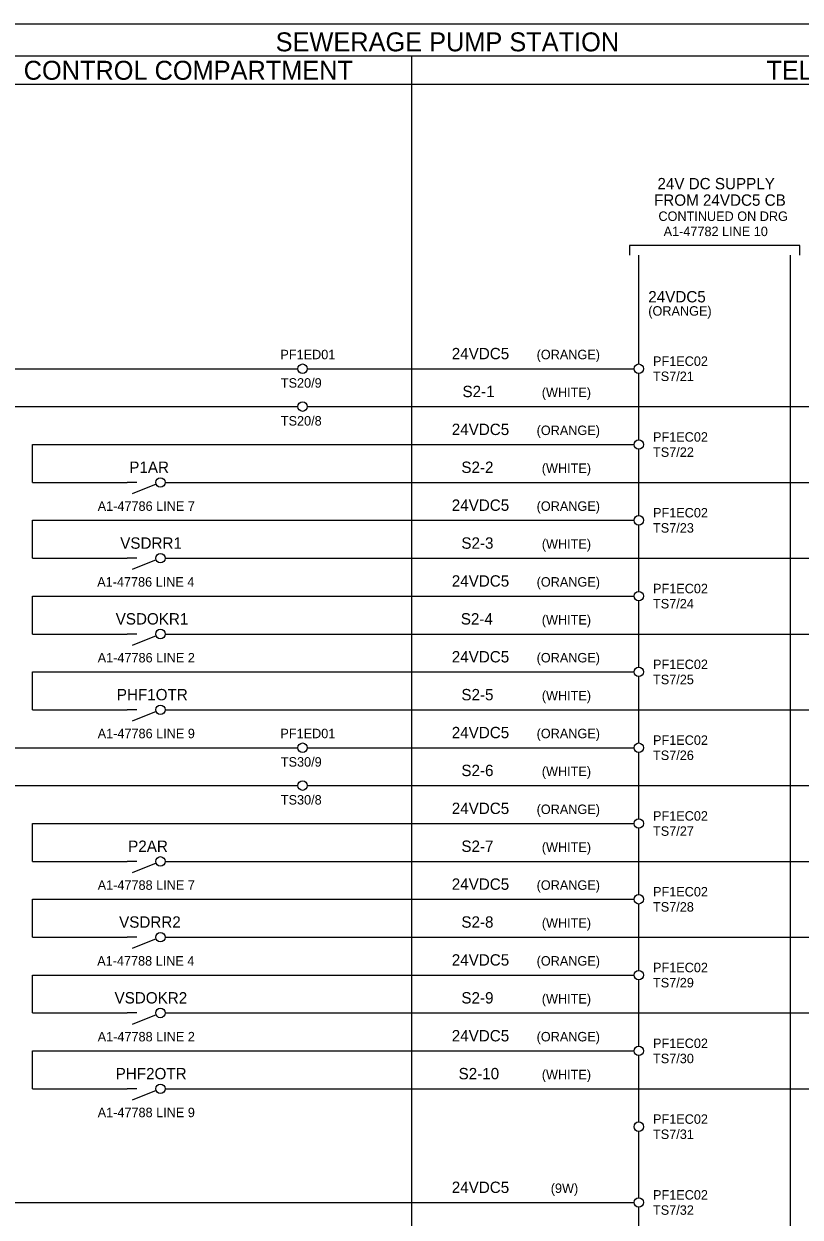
# Model space of a CAD drawing. Extents: x 0 to 841, y 0 to 594.
# Drawn here: x 447.7 to 652.6, y 266.1 to 581 of the extents above; entities that cross this region are included whole.
import ezdxf

# ---------------------------------------------------------------- set-up
doc = ezdxf.new("R2010")
doc.units = 0
for name, color, linetype in [('A1BORDER', 7, 'Continuous'), ('Default', 7, 'Continuous'), ('Level 1', 7, 'Continuous'), ('Level 10', 7, 'Continuous'), ('Level 2', 7, 'Continuous'), ('Level 5', 7, 'Continuous')]:
    doc.layers.add(name, color=color, linetype=linetype)

msp = doc.modelspace()

# ---------------------------------------------------------------- linework, layer by layer
at = {"layer": 'A1BORDER'}
msp.add_line((28, 581), (829, 581), dxfattribs=at)
at = {"layer": 'Default'}
msp.add_line((650, 140), (650, 520), dxfattribs=at)
at = {"layer": 'Level 1'}
for p, q in [((829, 572.5), (160, 572.5)), ((550, 572.5), (550, 57)), ((829, 565), (160, 565)), ((610, 491.25), (610, 520)), ((320, 490), (520, 490)), ((520, 490), (520, 490)), ((522.5, 490), (522.5, 490)), ((522.5, 490), (608.75, 490)), ((610, 471.25), (610, 488.75)), ((360, 480), (520, 480)), ((520, 480), (520, 480)), ((522.5, 480), (522.5, 480)), ((522.5, 480), (690, 480)), ((450, 460), (450, 470)), ((450, 470), (608.75, 470)), ((610, 451.25), (610, 468.75)), ((450, 460), (475, 460)), ((477.5, 460), (475, 460)), ((475, 460), (475, 460)), ((485, 460), (690, 460)), ((485, 460), (485, 460)), ((450, 440), (450, 450)), ((450, 450), (608.75, 450)), ((610, 431.25), (610, 448.75)), ((450, 440), (475, 440)), ((477.5, 440), (475, 440)), ((475, 440), (475, 440)), ((485, 440), (690, 440)), ((485, 440), (485, 440)), ((450, 430), (608.75, 430)), ((450, 420), (450, 430)), ((610, 411.25), (610, 428.75)), ((450, 420), (475, 420)), ((477.5, 420), (475, 420)), ((475, 420), (475, 420)), ((485, 420), (690, 420)), ((485, 420), (485, 420)), ((450, 410), (608.75, 410)), ((450, 400), (450, 410)), ((610, 391.25), (610, 408.75)), ((450, 400), (475, 400)), ((477.5, 400), (475, 400)), ((475, 400), (475, 400)), ((485, 400), (690, 400)), ((485, 400), (485, 400)), ((320, 390), (520, 390)), ((520, 390), (520, 390)), ((522.5, 390), (522.5, 390)), ((522.5, 390), (608.75, 390)), ((610, 371.25), (610, 388.75)), ((360, 380), (520, 380)), ((520, 380), (520, 380)), ((522.5, 380), (522.5, 380)), ((522.5, 380), (690, 380)), ((450, 360), (450, 370)), ((450, 370), (608.75, 370)), ((610, 351.25), (610, 368.75)), ((450, 360), (475, 360)), ((477.5, 360), (475, 360)), ((475, 360), (475, 360)), ((485, 360), (690, 360)), ((485, 360), (485, 360)), ((450, 340), (450, 350)), ((450, 350), (608.75, 350)), ((610, 331.25), (610, 348.75)), ((450, 340), (475, 340)), ((477.5, 340), (475, 340)), ((475, 340), (475, 340)), ((485, 340), (690, 340)), ((485, 340), (485, 340)), ((450, 330), (608.75, 330)), ((450, 320), (450, 330)), ((610, 311.25), (610, 328.75)), ((450, 320), (475, 320)), ((477.5, 320), (475, 320)), ((475, 320), (475, 320)), ((485, 320), (690, 320)), ((485, 320), (485, 320)), ((450, 310), (608.75, 310)), ((450, 300), (450, 310)), ((610, 291.25), (610, 308.75)), ((450, 300), (475, 300)), ((477.5, 300), (475, 300)), ((475, 300), (475, 300)), ((485, 300), (690, 300)), ((485, 300), (485, 300)), ((610, 271.25), (610, 288.75)), ((272.5, 270), (608.75, 270)), ((610, 251.25), (610, 268.75))]:
    msp.add_line(p, q, dxfattribs=at)
msp.add_lwpolyline([(652.5, 520), (652.5, 522.5), (607.5, 522.5), (607.5, 520)], dxfattribs=at)
at = {"layer": 'Level 10'}
for p, q in [((482.59, 459.54), (476.25, 457)), ((482.59, 439.54), (476.25, 437)), ((482.59, 419.54), (476.25, 417)), ((482.59, 399.54), (476.25, 397)), ((482.59, 359.54), (476.25, 357)), ((482.59, 339.54), (476.25, 337)), ((482.59, 319.54), (476.25, 317)), ((482.59, 299.54), (476.25, 297))]:
    msp.add_line(p, q, dxfattribs=at)
for centre in [(521.25, 490), (610, 490), (521.25, 480), (610, 470), (483.75, 460), (610, 450), (483.75, 440), (610, 430), (483.75, 420), (610, 410), (483.75, 400), (521.25, 390), (610, 390), (521.25, 380), (610, 370), (483.75, 360), (610, 350), (483.75, 340), (610, 330), (483.75, 320), (610, 310), (483.75, 300), (610, 290), (610, 270)]:
    msp.add_circle(centre, 1.25, dxfattribs=at)

# ---------------------------------------------------------------- texts
at = {"layer": 'Level 1'}
for s, height, p in [('SEWERAGE PUMP STATION', 5, (514.16, 573.75)), ('CONTROL COMPARTMENT', 5, (447.65, 566.25)), ('TELEMETRY COMPARTMENT', 5, (643.66, 566.25)), ('24V DC SUPPLY', 3, (614.91, 537.34)), ('FROM 24VDC5 CB', 3, (614.01, 533)), ('CONTINUED ON DRG', 2.5, (615.18, 529)), ('A1-47782 LINE 10', 2.5, (616.55, 525)), ('24VDC5', 3, (612.5, 507.5)), ('(ORANGE)', 2.5, (612.5, 504)), ('PF1ED01', 2.5, (515.4, 492.5)), ('24VDC5', 3, (560.63, 492.5)), ('(ORANGE)', 2.5, (583.03, 492.5)), ('PF1EC02', 2.5, (613.75, 490.75)), ('TS7/21', 2.5, (613.75, 486.75)), ('TS20/9', 2.5, (515.52, 485)), ('S2-1', 3, (563.46, 482.5)), ('(WHITE)', 2.5, (584.39, 482.5)), ('TS20/8', 2.5, (515.52, 475)), ('24VDC5', 3, (560.63, 472.5)), ('(ORANGE)', 2.5, (583.03, 472.5)), ('PF1EC02', 2.5, (613.75, 470.75)), ('TS7/22', 2.5, (613.75, 466.75)), ('S2-2', 3, (563.16, 462.5)), ('(WHITE)', 2.5, (584.39, 462.5)), ('24VDC5', 3, (560.63, 452.5)), ('(ORANGE)', 2.5, (583.03, 452.5)), ('PF1EC02', 2.5, (613.75, 450.75)), ('TS7/23', 2.5, (613.75, 446.75)), ('S2-3', 3, (563.17, 442.5)), ('(WHITE)', 2.5, (584.4, 442.5)), ('24VDC5', 3, (560.63, 432.5)), ('(ORANGE)', 2.5, (583.03, 432.5)), ('PF1EC02', 2.5, (613.75, 430.75)), ('TS7/24', 2.5, (613.75, 426.75)), ('S2-4', 3, (563.02, 422.5)), ('(WHITE)', 2.5, (584.4, 422.5)), ('24VDC5', 3, (560.63, 412.5)), ('(ORANGE)', 2.5, (583.03, 412.5)), ('PF1EC02', 2.5, (613.75, 410.75)), ('TS7/25', 2.5, (613.75, 406.75)), ('S2-5', 3, (563.17, 402.5)), ('(WHITE)', 2.5, (584.4, 402.5)), ('PF1ED01', 2.5, (515.4, 392.5)), ('24VDC5', 3, (560.63, 392.5)), ('(ORANGE)', 2.5, (583.03, 392.5)), ('PF1EC02', 2.5, (613.75, 390.75)), ('TS30/9', 2.5, (515.52, 385)), ('TS7/26', 2.5, (613.75, 386.75)), ('S2-6', 3, (563.17, 382.5)), ('(WHITE)', 2.5, (584.4, 382.5)), ('TS30/8', 2.5, (515.52, 375)), ('24VDC5', 3, (560.63, 372.5)), ('(ORANGE)', 2.5, (583.03, 372.5)), ('S2-7', 3, (563.17, 362.5)), ('(WHITE)', 2.5, (584.4, 362.5)), ('24VDC5', 3, (560.63, 352.5)), ('(ORANGE)', 2.5, (583.03, 352.5)), ('S2-8', 3, (563.17, 342.5)), ('(WHITE)', 2.5, (584.4, 342.5)), ('24VDC5', 3, (560.63, 332.5)), ('(ORANGE)', 2.5, (583.03, 332.5)), ('S2-9', 3, (563.17, 322.5)), ('(WHITE)', 2.5, (584.4, 322.5)), ('24VDC5', 3, (560.63, 312.5)), ('(ORANGE)', 2.5, (583.03, 312.5)), ('S2-10', 3, (562.43, 302.5)), ('(WHITE)', 2.5, (584.4, 302.5)), ('24VDC5', 3, (560.63, 272.5)), ('(9W)', 2.5, (586.76, 272.5))]:
    msp.add_text(s, height=height, dxfattribs=at).set_placement(p)
at = {"layer": 'Level 2'}
for s, p in [('PF1EC02', (613.75, 370.75)), ('TS7/27', (613.75, 366.75)), ('PF1EC02', (613.75, 350.75)), ('TS7/28', (613.75, 346.75)), ('PF1EC02', (613.75, 330.75)), ('TS7/29', (613.75, 326.75)), ('PF1EC02', (613.75, 310.75)), ('TS7/30', (613.75, 306.75)), ('PF1EC02', (613.75, 290.75)), ('TS7/31', (613.75, 286.75)), ('PF1EC02', (613.75, 270.75)), ('TS7/32', (613.75, 266.75))]:
    msp.add_text(s, height=2.5, dxfattribs=at).set_placement(p)
at = {"layer": 'Level 5'}
for s, height, p in [('P1AR', 3, (475.52, 462.5)), ('A1-47786 LINE 7', 2.5, (467.18, 452.5)), ('VSDRR1', 3, (473.13, 442.5)), ('A1-47786 LINE 4', 2.5, (467.05, 432.5)), ('VSDOKR1', 3, (471.93, 422.5)), ('A1-47786 LINE 2', 2.5, (467.18, 412.5)), ('PHF1OTR', 3, (472.23, 402.5)), ('A1-47786 LINE 9', 2.5, (467.18, 392.5)), ('P2AR', 3, (475.22, 362.5)), ('A1-47788 LINE 7', 2.5, (467.18, 352.5)), ('VSDRR2', 3, (472.83, 342.5)), ('A1-47788 LINE 4', 2.5, (467.05, 332.5)), ('VSDOKR2', 3, (471.63, 322.5)), ('A1-47788 LINE 2', 2.5, (467.18, 312.5)), ('PHF2OTR', 3, (471.93, 302.5)), ('A1-47788 LINE 9', 2.5, (467.18, 292.5))]:
    msp.add_text(s, height=height, dxfattribs=at).set_placement(p)

doc.saveas('drawing.dxf')
